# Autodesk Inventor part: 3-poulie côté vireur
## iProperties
Created: 2011-02
Part Number: 3-poulie côté vireur
Document SubType Name: Modeling
Designer: eric
Density: 1 g/cm^3
Author: eric
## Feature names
1. Base1
